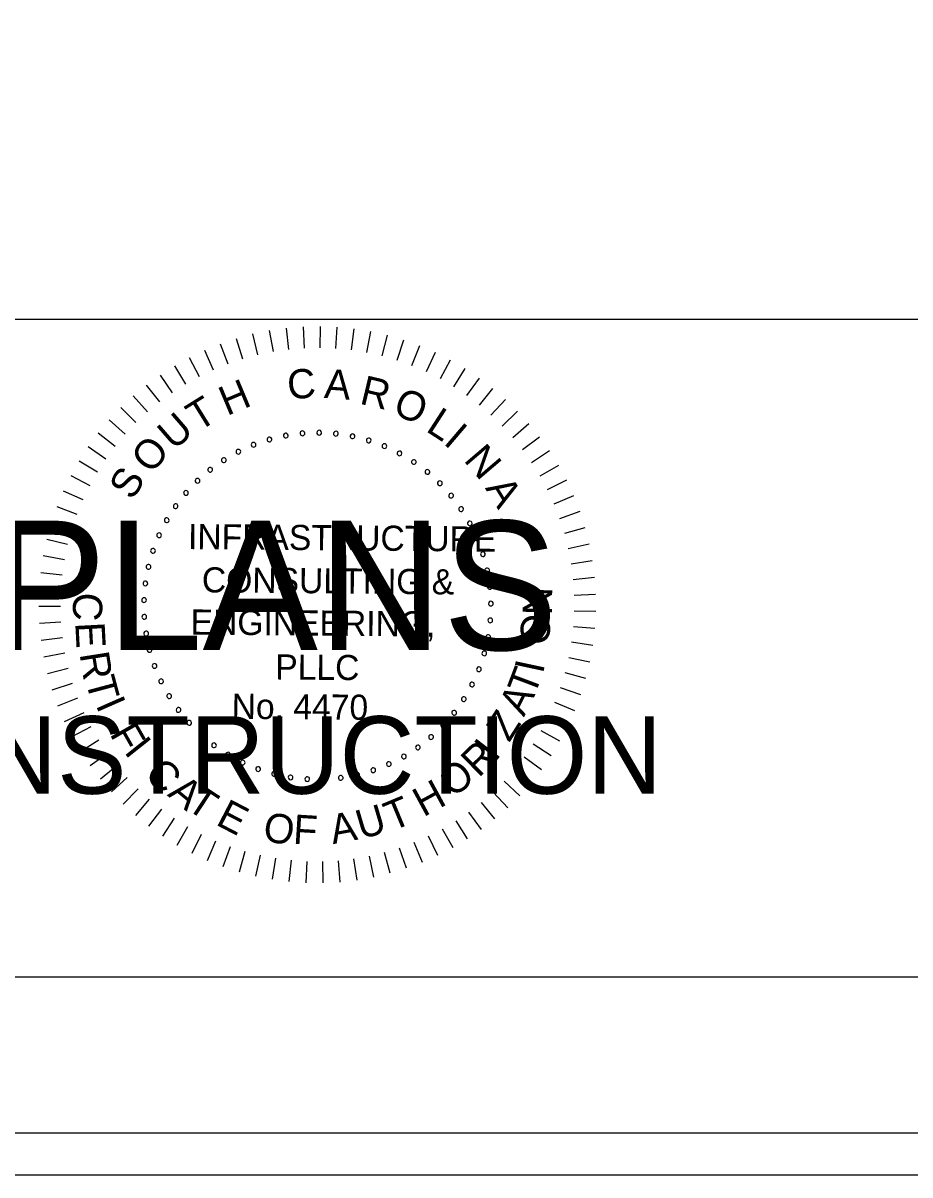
# Model space of a CAD drawing. Extents: x 967 to 1326, y 964 to 2864.
# Drawn here: x 1189.3 to 1212.88, y 1243.72 to 1274.36 of the extents above; entities that cross this region are included whole.
import ezdxf

# ---------------------------------------------------------------- set-up
doc = ezdxf.new("R2010")
doc.units = 0
for name, color, linetype in [('RD_PD_Final_TX', 7, 'Continuous'), ('RD_XS_TX_Elev_PR', 7, 'Continuous'), ('RD_XS_TX_Misc', 7, 'Continuous'), ('RD_XS_TX_ShdSlope', 7, 'Continuous')]:
    doc.layers.add(name, color=color, linetype=linetype)

msp = doc.modelspace()

# ---------------------------------------------------------------- linework, layer by layer
at = {"layer": 'RD_PD_Final_TX'}
for p, q in [((996.114, 1266.486), (1323.886, 1266.486)), ((1323.886, 1248.983), (996.114, 1248.983))]:
    msp.add_line(p, q, dxfattribs=at)
at = {"layer": 'RD_XS_TX_Elev_PR'}
for points in [[(967.409, 1243.72), (1326.285, 1243.72), (1326.285, 1463.72), (967.409, 1463.72)], [(988.525, 1244.84), (1326.285, 1244.84), (1326.285, 1462.6), (988.525, 1462.6)]]:
    msp.add_lwpolyline(points, close=True, dxfattribs=at)
at = {"layer": 'RD_XS_TX_ShdSlope'}
for p, q in [((1195.403, 1266.09), (1195.536, 1265.536)), ((1195.846, 1266.181), (1195.945, 1265.62)), ((1196.292, 1266.245), (1196.357, 1265.68)), ((1196.742, 1266.282), (1196.772, 1265.714)), ((1197.194, 1266.292), (1197.189, 1265.723)), ((1197.645, 1266.274), (1197.606, 1265.706)), ((1198.094, 1266.228), (1198.02, 1265.664)), ((1198.54, 1266.156), (1198.432, 1265.596)), ((1198.98, 1266.056), (1198.838, 1265.504)), ((1194.54, 1265.827), (1194.739, 1265.293)), ((1194.968, 1265.971), (1195.134, 1265.427)), ((1199.414, 1265.929), (1199.238, 1265.387)), ((1199.839, 1265.777), (1199.63, 1265.246)), ((1193.715, 1265.461), (1193.978, 1264.956)), ((1194.122, 1265.656), (1194.353, 1265.136)), ((1200.253, 1265.598), (1200.013, 1265.082)), ((1193.321, 1265.241), (1193.614, 1264.752)), ((1200.656, 1265.395), (1200.385, 1264.894)), ((1201.047, 1265.167), (1200.745, 1264.684)), ((1192.94, 1264.997), (1193.263, 1264.528)), ((1201.422, 1264.917), (1201.092, 1264.453)), ((1192.576, 1264.731), (1192.926, 1264.282)), ((1201.781, 1264.643), (1201.424, 1264.2)), ((1192.228, 1264.443), (1192.605, 1264.016)), ((1202.124, 1264.349), (1201.739, 1263.928)), ((1191.899, 1264.134), (1192.301, 1263.731)), ((1202.447, 1264.034), (1202.038, 1263.638)), ((1191.589, 1263.805), (1192.015, 1263.428)), ((1202.751, 1263.7), (1202.318, 1263.329)), ((1191.299, 1263.459), (1191.748, 1263.108)), ((1203.034, 1263.348), (1202.579, 1263.004)), ((1191.032, 1263.095), (1191.501, 1262.772)), ((1203.294, 1262.979), (1202.82, 1262.664)), ((1190.787, 1262.716), (1191.274, 1262.422)), ((1203.532, 1262.595), (1203.04, 1262.31)), ((1190.565, 1262.323), (1191.07, 1262.059)), ((1203.746, 1262.198), (1203.237, 1261.943)), ((1190.368, 1261.916), (1190.888, 1261.684)), ((1203.936, 1261.788), (1203.412, 1261.564)), ((1190.196, 1261.499), (1190.729, 1261.299)), ((1204.1, 1261.367), (1203.563, 1261.176)), ((1190.05, 1261.072), (1190.594, 1260.905)), ((1204.238, 1260.937), (1203.691, 1260.779)), ((1189.93, 1260.636), (1190.484, 1260.503)), ((1204.349, 1260.5), (1203.794, 1260.375)), ((1189.837, 1260.195), (1190.398, 1260.095)), ((1204.434, 1260.056), (1203.872, 1259.966)), ((1189.771, 1259.748), (1190.337, 1259.683)), ((1204.491, 1259.608), (1203.925, 1259.552)), ((1189.732, 1259.298), (1190.301, 1259.267)), ((1204.522, 1259.158), (1203.953, 1259.137)), ((1189.721, 1258.847), (1190.29, 1258.851)), ((1204.524, 1258.706), (1203.955, 1258.72)), ((1189.737, 1258.396), (1190.306, 1258.434)), ((1204.499, 1258.256), (1203.932, 1258.304)), ((1189.781, 1257.946), (1190.346, 1258.019)), ((1204.447, 1257.807), (1203.884, 1257.89)), ((1189.852, 1257.5), (1190.412, 1257.608)), ((1204.367, 1257.363), (1203.81, 1257.479)), ((1189.951, 1257.06), (1190.502, 1257.201)), ((1204.261, 1256.924), (1203.712, 1257.074)), ((1190.076, 1256.626), (1190.617, 1256.8)), ((1204.128, 1256.492), (1203.589, 1256.676)), ((1190.227, 1256.2), (1190.757, 1256.408)), ((1203.969, 1256.07), (1203.442, 1256.286)), ((1190.403, 1255.785), (1190.92, 1256.024)), ((1190.605, 1255.381), (1191.106, 1255.651)), ((1203.784, 1255.658), (1203.271, 1255.906)), ((1203.574, 1255.258), (1203.078, 1255.537)), ((1190.831, 1254.99), (1191.315, 1255.291)), ((1203.341, 1254.871), (1202.862, 1255.18)), ((1191.081, 1254.614), (1191.545, 1254.943)), ((1203.085, 1254.5), (1202.626, 1254.837)), ((1191.353, 1254.253), (1191.796, 1254.61)), ((1202.806, 1254.145), (1202.368, 1254.509)), ((1191.646, 1253.91), (1192.067, 1254.293)), ((1202.506, 1253.807), (1202.092, 1254.197)), ((1191.96, 1253.585), (1192.356, 1253.994)), ((1202.186, 1253.488), (1201.796, 1253.903)), ((1192.293, 1253.28), (1192.664, 1253.712)), ((1201.847, 1253.19), (1201.484, 1253.628)), ((1192.644, 1252.996), (1192.988, 1253.45)), ((1193.011, 1252.734), (1193.327, 1253.208)), ((1201.491, 1252.912), (1201.155, 1253.372)), ((1193.394, 1252.495), (1193.68, 1252.987)), ((1200.731, 1252.425), (1200.453, 1252.922)), ((1201.119, 1252.657), (1200.811, 1253.136)), ((1193.791, 1252.279), (1194.047, 1252.788)), ((1194.2, 1252.088), (1194.424, 1252.612)), ((1199.918, 1252.034), (1199.702, 1252.561)), ((1200.331, 1252.217), (1200.083, 1252.73)), ((1194.62, 1251.923), (1194.812, 1252.459)), ((1195.05, 1251.783), (1195.208, 1252.33)), ((1199.063, 1251.745), (1198.913, 1252.295)), ((1199.495, 1251.877), (1199.312, 1252.416)), ((1195.487, 1251.67), (1195.612, 1252.225)), ((1195.93, 1251.584), (1196.021, 1252.146)), ((1196.377, 1251.524), (1196.434, 1252.091)), ((1196.828, 1251.493), (1196.85, 1252.062)), ((1197.279, 1251.488), (1197.267, 1252.058)), ((1197.73, 1251.512), (1197.683, 1252.079)), ((1198.179, 1251.562), (1198.097, 1252.126)), ((1198.624, 1251.64), (1198.508, 1252.198))]:
    msp.add_line(p, q, dxfattribs=at)
for centre, start, end in [((1195.851, 1263.285), 16.1422, 196.1422), ((1195.851, 1263.285), 196.1422, 16.1422), ((1196.285, 1263.388), 10.6038, 190.6038), ((1196.285, 1263.388), 190.6038, 10.6038), ((1196.727, 1263.447), 5.0653, 185.0653), ((1196.727, 1263.447), 185.0653, 5.0653), ((1197.172, 1263.464), 359.5268, 179.5268), ((1197.172, 1263.464), 179.5268, 359.5268), ((1197.617, 1263.438), 173.9884, 353.9884), ((1197.617, 1263.438), 353.9884, 173.9884), ((1198.057, 1263.369), 168.4499, 348.4499), ((1198.057, 1263.369), 348.4499, 168.4499), ((1198.489, 1263.258), 342.9114, 162.9114), ((1195.023, 1262.958), 27.2191, 207.2191), ((1195.023, 1262.958), 207.2191, 27.2191), ((1195.429, 1263.142), 21.6807, 201.6807), ((1195.429, 1263.142), 201.6807, 21.6807), ((1198.489, 1263.258), 162.9114, 342.9114), ((1198.908, 1263.106), 157.373, 337.373), ((1198.908, 1263.106), 337.373, 157.373), ((1199.31, 1262.914), 331.8345, 151.8345), ((1194.637, 1262.736), 32.7576, 212.7576), ((1194.637, 1262.736), 212.7576, 32.7576), ((1199.31, 1262.914), 151.8345, 331.8345), ((1199.692, 1262.684), 146.2961, 326.2961), ((1199.692, 1262.684), 326.2961, 146.2961), ((1194.274, 1262.478), 38.2961, 218.2961), ((1194.274, 1262.478), 218.2961, 38.2961), ((1200.05, 1262.419), 140.7576, 320.7576), ((1200.05, 1262.419), 320.7576, 140.7576), ((1193.937, 1262.186), 43.8345, 223.8345), ((1193.937, 1262.186), 223.8345, 43.8345), ((1200.38, 1262.12), 135.2191, 315.2191), ((1200.38, 1262.12), 315.2191, 135.2191), ((1193.63, 1261.862), 49.373, 229.373), ((1193.63, 1261.862), 229.373, 49.373), ((1200.68, 1261.79), 129.6807, 309.6807), ((1200.68, 1261.79), 309.6807, 129.6807), ((1193.356, 1261.511), 54.9114, 234.9114), ((1193.356, 1261.511), 234.9114, 54.9114), ((1200.947, 1261.433), 124.1422, 304.1422), ((1200.947, 1261.433), 304.1422, 124.1422), ((1193.117, 1261.135), 60.4499, 240.4499), ((1193.117, 1261.135), 240.4499, 60.4499), ((1201.179, 1261.052), 118.6038, 298.6038), ((1201.179, 1261.052), 298.6038, 118.6038), ((1192.915, 1260.737), 65.9884, 245.9884), ((1192.915, 1260.737), 245.9884, 65.9884), ((1201.372, 1260.651), 113.0653, 293.0653), ((1201.372, 1260.651), 293.0653, 113.0653), ((1192.753, 1260.322), 71.5268, 251.5268), ((1192.753, 1260.322), 251.5268, 71.5268), ((1201.526, 1260.233), 107.5268, 287.5268), ((1201.526, 1260.233), 287.5268, 107.5268), ((1192.632, 1259.894), 77.0653, 257.0653), ((1192.632, 1259.894), 257.0653, 77.0653), ((1201.638, 1259.801), 101.9884, 281.9884), ((1201.638, 1259.801), 281.9884, 101.9884), ((1192.552, 1259.455), 82.6038, 262.6038), ((1192.552, 1259.455), 262.6038, 82.6038), ((1201.709, 1259.361), 96.4499, 276.4499), ((1201.709, 1259.361), 276.4499, 96.4499), ((1192.515, 1259.011), 88.1422, 268.1422), ((1192.515, 1259.011), 268.1422, 88.1422), ((1201.737, 1258.917), 90.9114, 270.9114), ((1201.737, 1258.917), 270.9114, 90.9114), ((1192.522, 1258.565), 93.6807, 273.6807), ((1192.522, 1258.565), 273.6807, 93.6807), ((1201.721, 1258.471), 85.373, 265.373), ((1201.721, 1258.471), 265.373, 85.373), ((1192.571, 1258.122), 99.2191, 279.2191), ((1192.571, 1258.122), 279.2191, 99.2191), ((1201.663, 1258.029), 79.8345, 259.8345), ((1201.663, 1258.029), 259.8345, 79.8345), ((1192.662, 1257.686), 104.7576, 284.7576), ((1192.662, 1257.686), 284.7576, 104.7576), ((1201.563, 1257.595), 74.2961, 254.2961), ((1201.563, 1257.595), 254.2961, 74.2961), ((1192.796, 1257.261), 110.2961, 290.2961), ((1192.796, 1257.261), 290.2961, 110.2961), ((1201.42, 1257.173), 68.7576, 248.7576), ((1201.42, 1257.173), 248.7576, 68.7576), ((1192.97, 1256.851), 115.8345, 295.8345), ((1192.97, 1256.851), 295.8345, 115.8345), ((1201.238, 1256.766), 63.2191, 243.2191), ((1201.238, 1256.766), 243.2191, 63.2191), ((1193.182, 1256.459), 121.373, 301.373), ((1193.182, 1256.459), 301.373, 121.373), ((1201.018, 1256.379), 57.6807, 237.6807), ((1201.018, 1256.379), 237.6807, 57.6807), ((1193.432, 1256.09), 126.9114, 306.9114), ((1193.432, 1256.09), 306.9114, 126.9114), ((1200.761, 1256.014), 52.1422, 232.1422), ((1200.761, 1256.014), 232.1422, 52.1422), ((1193.715, 1255.746), 132.4499, 312.4499), ((1193.715, 1255.746), 312.4499, 132.4499), ((1200.47, 1255.677), 46.6038, 226.6038), ((1200.47, 1255.677), 226.6038, 46.6038), ((1194.031, 1255.431), 137.9884, 317.9884), ((1194.031, 1255.431), 317.9884, 137.9884), ((1200.148, 1255.369), 41.0653, 221.0653), ((1200.148, 1255.369), 221.0653, 41.0653), ((1194.376, 1255.149), 143.5268, 323.5268), ((1194.376, 1255.149), 323.5268, 143.5268), ((1199.798, 1255.093), 35.5268, 215.5268), ((1199.798, 1255.093), 215.5268, 35.5268), ((1194.746, 1254.901), 149.0653, 329.0653), ((1194.746, 1254.901), 329.0653, 149.0653), ((1195.139, 1254.69), 154.6038, 334.6038), ((1195.139, 1254.69), 334.6038, 154.6038), ((1199.026, 1254.65), 24.4499, 204.4499), ((1199.422, 1254.853), 29.9884, 209.9884), ((1199.422, 1254.853), 209.9884, 29.9884), ((1195.55, 1254.517), 160.1422, 340.1422), ((1195.55, 1254.517), 340.1422, 160.1422), ((1195.975, 1254.386), 165.6807, 345.6807), ((1195.975, 1254.386), 345.6807, 165.6807), ((1198.183, 1254.363), 13.373, 193.373), ((1198.611, 1254.486), 18.9114, 198.9114), ((1198.611, 1254.486), 198.9114, 18.9114), ((1199.026, 1254.65), 204.4499, 24.4499), ((1196.412, 1254.295), 171.2191, 351.2191), ((1196.412, 1254.295), 351.2191, 171.2191), ((1196.855, 1254.248), 356.7576, 176.7576), ((1196.855, 1254.248), 176.7576, 356.7576), ((1197.301, 1254.243), 2.2961, 182.2961), ((1197.301, 1254.243), 182.2961, 2.2961), ((1197.745, 1254.282), 7.8345, 187.8345), ((1197.745, 1254.282), 187.8345, 7.8345), ((1198.183, 1254.363), 193.373, 13.373)]:
    msp.add_arc(centre, 0.0627, start, end, dxfattribs=at)

# ---------------------------------------------------------------- texts
at = {"layer": 'RD_XS_TX_Misc'}
for s, height, p in [('FINAL PLANS', 3.4375, (1174.145, 1257.685)), ('NOT FOR CONSTRUCTION', 2.0625, (1170.901, 1253.86))]:
    msp.add_text(s, height=height, dxfattribs=at).set_placement(p)
at = {"layer": 'RD_XS_TX_ShdSlope'}
for s, height, rotation, p in [('C', 0.78, 4.7281, (1196.355, 1264.346)), ('A', 0.78, 355.6981, (1197.29, 1264.39)), ('H', 0.78, 22.7882, (1194.72, 1263.904)), ('R', 0.78, 346.6681, (1198.222, 1264.238)), ('O', 0.78, 337.638, (1199.096, 1263.972)), ('T', 0.78, 31.8182, (1193.961, 1263.478)), ('U', 0.78, 40.8482, (1193.306, 1262.976)), ('L', 0.78, 327.108, (1199.981, 1263.52)), ('I', 0.78, 319.578, (1200.451, 1263.182)), ('O', 0.78, 49.8782, (1192.707, 1262.341)), ('N', 0.78, 310.548, (1200.994, 1262.728)), ('S', 0.78, 58.9083, (1192.211, 1261.642)), ('A', 0.78, 301.5179, (1201.576, 1261.991)), ('INFRASTRUCTURE', 0.66873, 359.5268, (1193.682, 1260.367)), ('CONSULTING &', 0.66873, 359.5268, (1194.051, 1259.217)), ('C', 0.78, 267.025, (1190.646, 1259.227)), ('N', 0.78, 89.2085, (1203.359, 1258.604)), ('ENGINEERING,', 0.66873, 359.5268, (1193.751, 1258.095)), ('O', 0.78, 83.2085, (1203.26, 1257.786)), ('E', 0.78, 273.025, (1190.685, 1258.408)), ('R', 0.78, 279.025, (1190.799, 1257.583)), ('PLLC', 0.6687, 359.5268, (1196.002, 1256.9)), ('T', 0.78, 69.3954, (1202.891, 1256.428)), ('I', 0.78, 77.9093, (1203.121, 1257.032)), ('T', 0.78, 285.025, (1190.955, 1256.878)), ('A', 0.78, 63.3954, (1202.616, 1255.888)), ('I', 0.78, 293.7713, (1191.221, 1256.225)), ('No. 4470', 0.6687, 359.5268, (1194.843, 1255.855)), ('Z', 0.78, 57.3954, (1202.224, 1255.206)), ('F', 0.78, 299.7713, (1191.589, 1255.455)), ('I', 0.78, 308.5268, (1191.965, 1254.973)), ('I', 0.78, 52.3339, (1201.856, 1254.69)), ('R', 0.78, 44.5268, (1201.415, 1254.267)), ('C', 0.78, 314.5268, (1192.496, 1254.346)), ('O', 0.78, 38.5268, (1200.73, 1253.731)), ('A', 0.78, 320.5268, (1193.115, 1253.822)), ('T', 0.78, 326.5268, (1193.602, 1253.478)), ('H', 0.78, 28.5268, (1199.942, 1253.23)), ('T', 0.78, 22.5268, (1199.108, 1252.856)), ('E', 0.78, 332.5268, (1194.394, 1253.051)), ('U', 0.78, 16.5268, (1198.288, 1252.638)), ('O', 0.78, 350.5268, (1195.647, 1252.614)), ('F', 0.78, 356.5268, (1196.465, 1252.532)), ('A', 0.78, 10.5268, (1197.537, 1252.517))]:
    msp.add_text(s, height=height, rotation=rotation, dxfattribs=at).set_placement(p)

doc.saveas('drawing.dxf')
